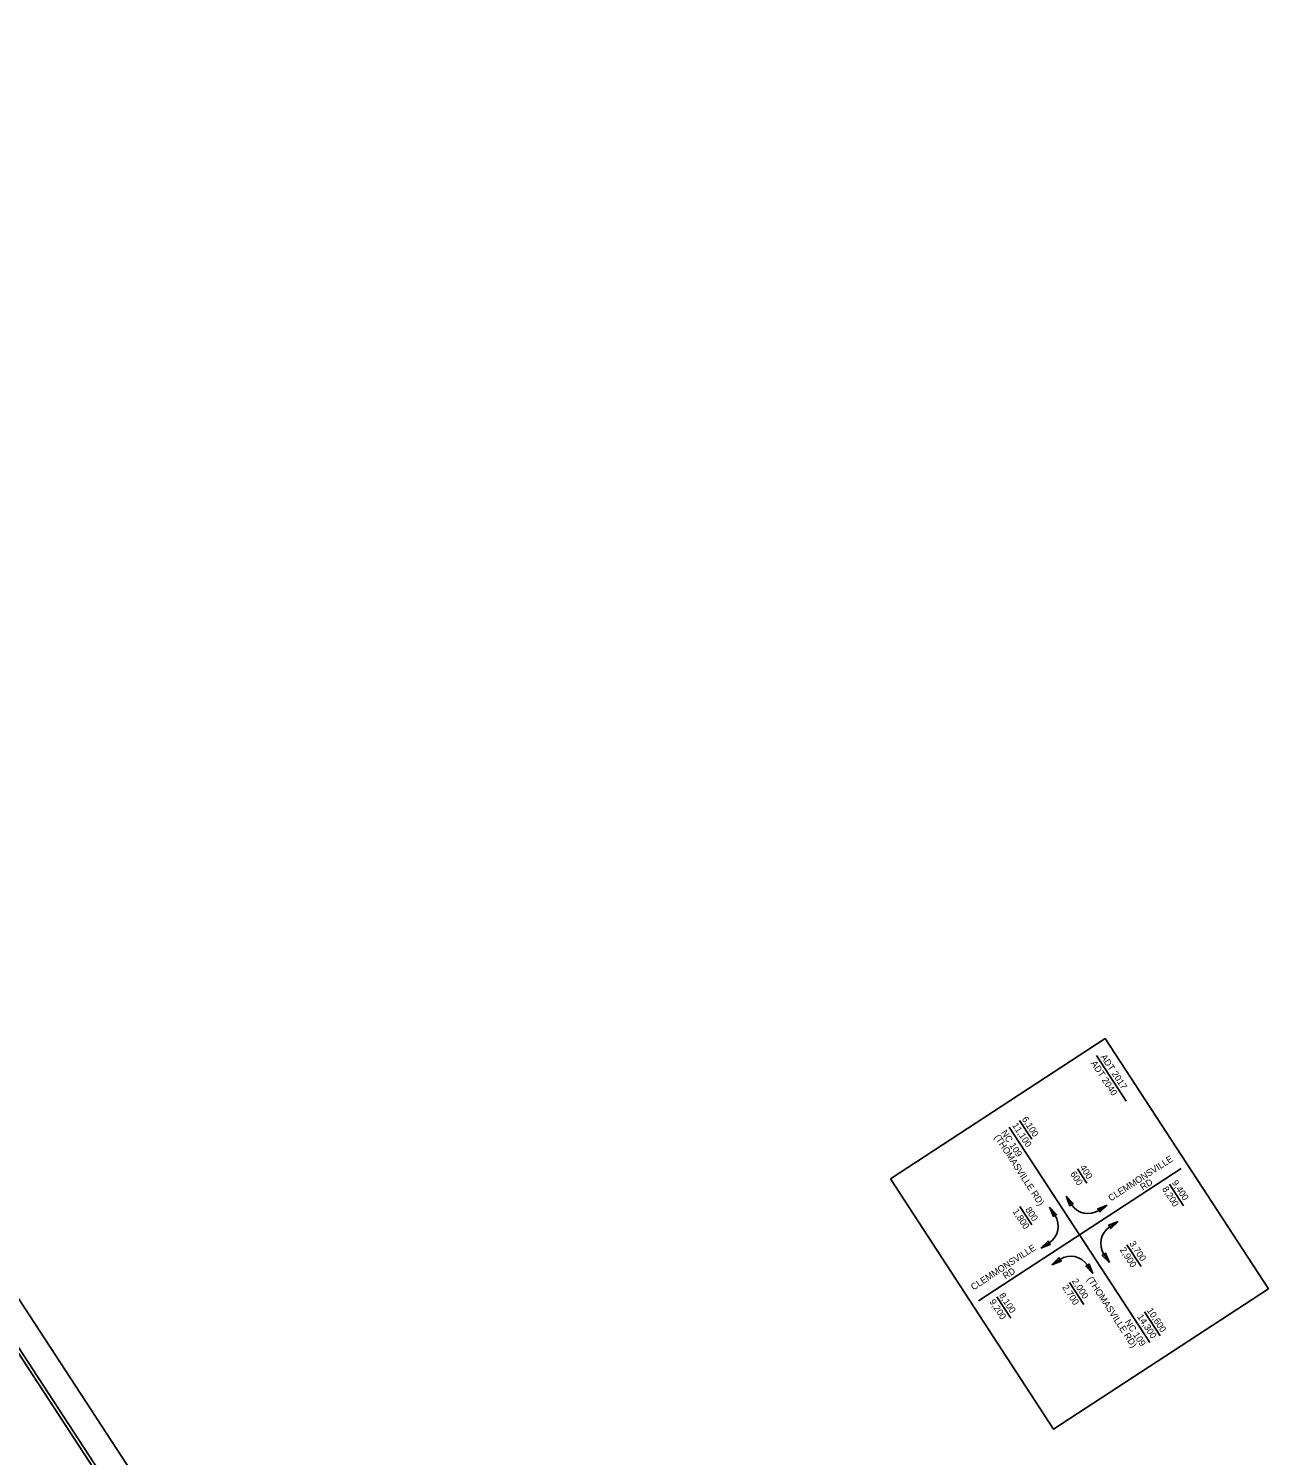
# Model space of a CAD drawing. Extents: x 1639622 to 2864602, y 842655 to 973236.
# Drawn here: x 1641175 to 1642115, y 843581 to 844663 of the extents above; entities that cross this region are included whole.
import ezdxf

# ---------------------------------------------------------------- set-up
doc = ezdxf.new("R2010")
doc.units = 0
for name, color, linetype in [('Default', 7, 'Continuous'), ('Sheet Plan CELL', 7, 'Continuous'), ('Sheet Plot Border Inside CELL', 7, 'Continuous'), ('Sheet Plot Border Outside CELL', 7, 'Continuous')]:
    doc.layers.add(name, color=color, linetype=linetype)

msp = doc.modelspace()

# ---------------------------------------------------------------- linework, layer by layer
at = {"layer": 'Default'}
for p, q in [((1641984.1, 843884.7), (1642006.8, 843850)), ((1641918, 843830.3), (1642024.6, 843667)), ((1641925.9, 843835.4), (1641935.1, 843821.2)), ((1642048.3, 843798.9), (1641894.7, 843698.7)), ((1641969.8, 843798.7), (1641976.8, 843787.9)), ((1642039.5, 843787.2), (1642050.2, 843770.8)), ((1641965.3, 843771.6), (1641961.2, 843777.9)), ((1641935.3, 843756.2), (1641926.1, 843770.2)), ((1641952.7, 843763.4), (1641948.6, 843769.7)), ((1641986, 843767.2), (1641992.3, 843771.3)), ((1641994.2, 843754.7), (1642000.5, 843758.8)), ((1641948.4, 843742.6), (1641942.1, 843738.5)), ((1642007.3, 843741.1), (1642018, 843724.7)), ((1641956.6, 843730.1), (1641950.3, 843726)), ((1641989.9, 843733.9), (1641994, 843727.6)), ((1641977.3, 843725.7), (1641981.4, 843719.4)), ((1641963.7, 843712.6), (1641974.6, 843695.9)), ((1641919.2, 843685.4), (1641908.6, 843701.7)), ((1642020.5, 843690.4), (1642032.4, 843672.1))]:
    msp.add_line(p, q, dxfattribs=at)
for points in [[(1641828, 843791.2), (1641990.7, 843897.4), (1642114.5, 843707.8), (1641951.7, 843601.5)], [(1641961.2, 843777.9), (1641966.5, 843772.4), (1641964, 843770.8)], [(1641948.6, 843769.7), (1641951.5, 843762.6), (1641954, 843764.2)], [(1641992.3, 843771.3), (1641986.9, 843766), (1641985.2, 843768.5)], [(1642000.5, 843758.8), (1641993.4, 843755.9), (1641995.1, 843753.4)], [(1641942.1, 843738.5), (1641949.2, 843741.4), (1641947.5, 843743.9)], [(1641950.3, 843726), (1641955.7, 843731.3), (1641957.4, 843728.8)], [(1641994, 843727.6), (1641991.1, 843734.7), (1641988.6, 843733.1)], [(1641981.4, 843719.4), (1641976.1, 843724.9), (1641978.6, 843726.5)]]:
    msp.add_lwpolyline(points, close=True, dxfattribs=at)
for centre, start, end in [((1641940.2, 843755.2), 303.1259, 33.1259), ((1641977.8, 843779.8), 213.1259, 303.1259), ((1642002.4, 843742.1), 123.1259, 213.1259), ((1641964.8, 843717.5), 33.1259, 123.1259)]:
    msp.add_arc(centre, 15, start, end, dxfattribs=at)
at = {"layer": 'Sheet Plan CELL'}
for points in [[(1641430.7, 843255.1), (1640611, 844511.4), (1639731.7, 843937.6), (1640551.4, 842681.3)], [(1639731.7, 843937.6), (1640611, 844511.4), (1641321.4, 843422.7), (1641195.7, 843340.7), (1641305.1, 843173.1), (1640551.4, 842681.3)]]:
    msp.add_lwpolyline(points, close=True, dxfattribs=at)
at = {"layer": 'Sheet Plot Border Inside CELL'}
msp.add_lwpolyline([(1639645.7, 844064.7), (1640556.1, 842669.5), (1641439.6, 843246), (1640529.2, 844641.3)], close=True, dxfattribs=at)
at = {"layer": 'Sheet Plot Border Outside CELL'}
msp.add_lwpolyline([(1639621.8, 844064.7), (1640541.8, 842654.8), (1641458.9, 843253.2), (1640538.9, 844663.1)], close=True, dxfattribs=at)
msp.add_lwpolyline([(1639621.8, 844064.7), (1640541.8, 842654.8), (1641458.9, 843253.2), (1640538.9, 844663.1)], close=True, dxfattribs=at)

# ---------------------------------------------------------------- texts
at = {"layer": 'Default'}
for s, rotation, p in [('ADT 2017', 303.1259, (1641987.1, 843883.6)), ('ADT 2040', 303.1259, (1641979.7, 843878.8)), ('6,100', 303.1259, (1641927.4, 843836.4)), ('NC 109', 303.1259, (1641911.7, 843826.2)), ('11,100', 303.1259, (1641920.1, 843831.7)), ('(THOMASVILLE RD)', 303.1259, (1641906.5, 843822.8)), ('CLEMMONSVILLE', 33.1259, (1641995.1, 843773.9)), ('600', 303.1259, (1641964, 843794.9)), ('400', 303.1259, (1641971.3, 843799.7)), ('RD', 33.1259, (1642019.3, 843782.2)), ('8,200', 303.1259, (1642033.7, 843783.4)), ('9,400', 303.1259, (1642041.1, 843788.2)), ('1,800', 303.1259, (1641920.4, 843766.4)), ('800', 303.1259, (1641930, 843767.8)), ('CLEMMONSVILLE', 33.1259, (1641891, 843706.5)), ('3,700', 303.1259, (1642008.9, 843742.1)), ('2,900', 303.1259, (1642001.6, 843737.3)), ('RD', 33.1259, (1641915.2, 843714.8)), ('2,700', 303.1259, (1641958, 843708.9)), ('2,000', 303.1259, (1641965.3, 843713.6)), ('(THOMASVILLE RD)', 303.1259, (1641976.8, 843715.1)), ('9,200', 303.1259, (1641902.8, 843698)), ('8,100', 303.1259, (1641910.1, 843702.8)), ('14,300', 303.1259, (1642014.8, 843686.6)), ('10,600', 303.1259, (1642022.1, 843691.4)), ('NC 109', 303.1259, (1642005.4, 843682.6))]:
    msp.add_text(s, height=5, rotation=rotation, dxfattribs=at).set_placement(p)

doc.saveas('drawing.dxf')
